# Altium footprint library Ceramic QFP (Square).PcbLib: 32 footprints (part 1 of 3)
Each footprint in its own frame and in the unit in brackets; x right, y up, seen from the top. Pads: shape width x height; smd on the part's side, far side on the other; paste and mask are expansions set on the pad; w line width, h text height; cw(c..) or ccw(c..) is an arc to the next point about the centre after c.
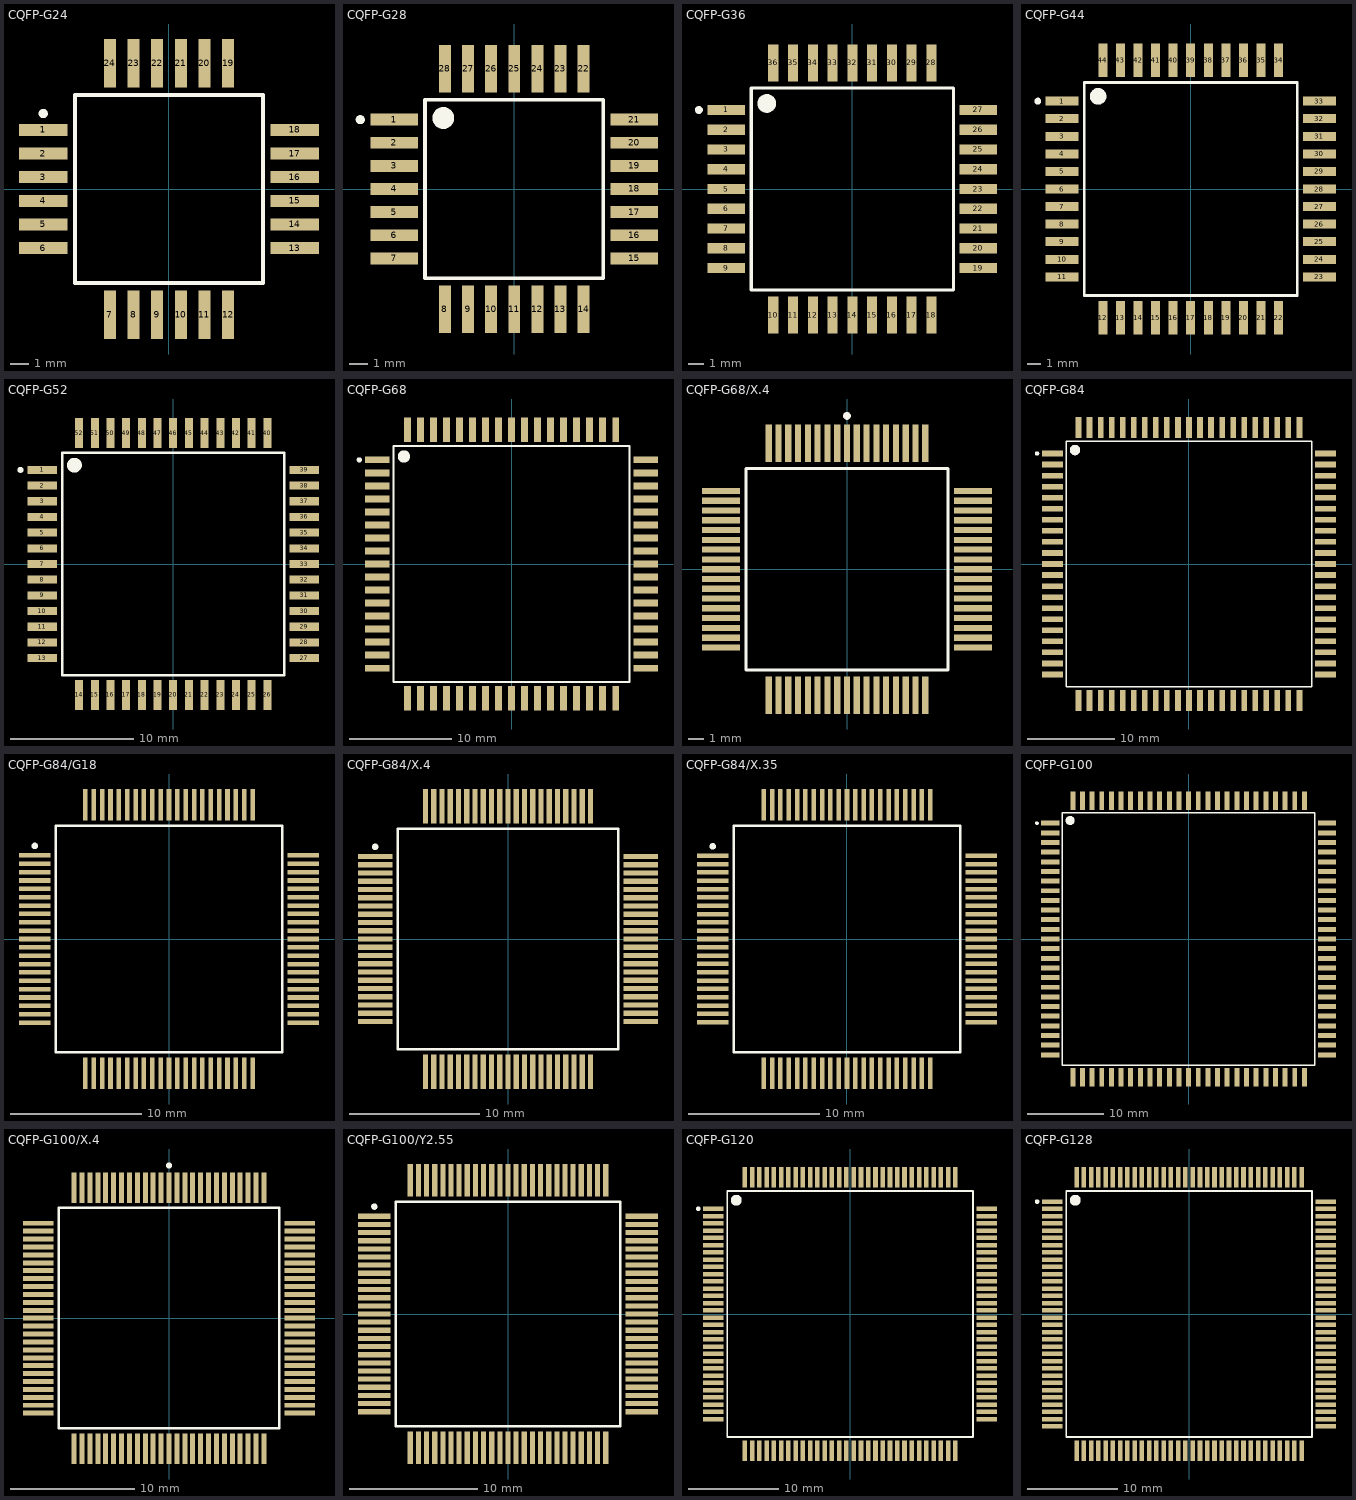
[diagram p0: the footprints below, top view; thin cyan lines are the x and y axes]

## CQFP-G24 [mm]
pads (24):
  rect 2.6x0.65 smd: 1(-6.75,3.175) 2(-6.75,1.905) 3(-6.75,0.635) 4(-6.75,-0.635) 5(-6.75,-1.905) 6(-6.75,-3.175) 13(6.75,-3.175) 14(6.75,-1.905) 15(6.75,-0.635) 16(6.75,0.635) 17(6.75,1.905) 18(6.75,3.175)
  rect 0.65x2.6 smd: 7(-3.175,-6.75) 8(-1.905,-6.75) 9(-0.635,-6.75) 10(0.635,-6.75) 11(1.905,-6.75) 12(3.175,-6.75) 19(3.175,6.75) 20(1.905,6.75) 21(0.635,6.75) 22(-0.635,6.75) 23(-1.905,6.75) 24(-3.175,6.75)
Top Overlay:
  circle w0.25: c-6.75,4.05 r0.125
  lines w0.2: -5.05,-5.05 -5.05,5.05 5.05,5.05 5.05,-5.05 -5.05,-5.05

## CQFP-G28 [mm]
pads (28):
  rect 2.6x0.65 smd: 1(-6.6,3.81) 2(-6.6,2.54) 3(-6.6,1.27) 4(-6.6,0) 5(-6.6,-1.27) 6(-6.6,-2.54) 7(-6.6,-3.81) 15(6.6,-3.81) 16(6.6,-2.54) 17(6.6,-1.27) 18(6.6,0) 19(6.6,1.27) 20(6.6,2.54) 21(6.6,3.81)
  rect 0.65x2.6 smd: 8(-3.81,-6.6) 9(-2.54,-6.6) 10(-1.27,-6.6) 11(0,-6.6) 12(1.27,-6.6) 13(2.54,-6.6) 14(3.81,-6.6) 22(3.81,6.6) 23(2.54,6.6) 24(1.27,6.6) 25(0,6.6) 26(-1.27,6.6) 27(-2.54,6.6) 28(-3.81,6.6)
Top Overlay:
  circle w0.25: c-8.46,3.81 r0.125
  circle w0.6: c-3.9,3.9 r0.3
  lines w0.2: -4.9,-4.9 4.9,-4.9 4.9,4.9 -4.9,4.9 -4.9,-4.9

## CQFP-G36 [mm]
pads (36):
  rect 2.4x0.65 smd: 1(-8.1,5.08) 2(-8.1,3.81) 3(-8.1,2.54) 4(-8.1,1.27) 5(-8.1,0) 6(-8.1,-1.27) 7(-8.1,-2.54) 8(-8.1,-3.81) 9(-8.1,-5.08) 19(8.1,-5.08) 20(8.1,-3.81) 21(8.1,-2.54) 22(8.1,-1.27) 23(8.1,0) 24(8.1,1.27) 25(8.1,2.54) 26(8.1,3.81) 27(8.1,5.08)
  rect 0.65x2.4 smd: 10(-5.08,-8.1) 11(-3.81,-8.1) 12(-2.54,-8.1) 13(-1.27,-8.1) 14(0,-8.1) 15(1.27,-8.1) 16(2.54,-8.1) 17(3.81,-8.1) 18(5.08,-8.1) 28(5.08,8.1) 29(3.81,8.1) 30(2.54,8.1) 31(1.27,8.1) 32(0,8.1) 33(-1.27,8.1) 34(-2.54,8.1) 35(-3.81,8.1) 36(-5.08,8.1)
Top Overlay:
  circle w0.25: c-9.86,5.08 r0.125
  circle w0.6: c-5.5,5.5 r0.3
  lines w0.2: -6.5,-6.5 6.5,-6.5 6.5,6.5 -6.5,6.5 -6.5,-6.5

## CQFP-G44 [mm]
pads (44):
  rect 2.4x0.65 smd: 1(-9.3,6.35) 2(-9.3,5.08) 3(-9.3,3.81) 4(-9.3,2.54) 5(-9.3,1.27) 6(-9.3,0) 7(-9.3,-1.27) 8(-9.3,-2.54) 9(-9.3,-3.81) 10(-9.3,-5.08) 11(-9.3,-6.35) 23(9.3,-6.35) 24(9.3,-5.08) 25(9.3,-3.81) 26(9.3,-2.54) 27(9.3,-1.27) 28(9.3,0) 29(9.3,1.27) 30(9.3,2.54) 31(9.3,3.81) 32(9.3,5.08) 33(9.3,6.35)
  rect 0.65x2.4 smd: 12(-6.35,-9.3) 13(-5.08,-9.3) 14(-3.81,-9.3) 15(-2.54,-9.3) 16(-1.27,-9.3) 17(0,-9.3) 18(1.27,-9.3) 19(2.54,-9.3) 20(3.81,-9.3) 21(5.08,-9.3) 22(6.35,-9.3) 34(6.35,9.3) 35(5.08,9.3) 36(3.81,9.3) 37(2.54,9.3) 38(1.27,9.3) 39(0,9.3) 40(-1.27,9.3) 41(-2.54,9.3) 42(-3.81,9.3) 43(-5.08,9.3) 44(-6.35,9.3)
Top Overlay:
  circle w0.6: c-6.7,6.7 r0.3
  circle w0.25: c-11.06,6.35 r0.125
  lines w0.2: -7.7,-7.7 -7.7,7.7 7.7,7.7 7.7,-7.7 -7.7,-7.7

## CQFP-G52 [mm]
pads (52):
  rect 2.4x0.65 smd: 1(-10.6,7.62) 2(-10.6,6.35) 3(-10.6,5.08) 4(-10.6,3.81) 5(-10.6,2.54) 6(-10.6,1.27) 7(-10.6,0) 8(-10.6,-1.27) 9(-10.6,-2.54) 10(-10.6,-3.81) 11(-10.6,-5.08) 12(-10.6,-6.35) 13(-10.6,-7.62) 27(10.6,-7.62) 28(10.6,-6.35) 29(10.6,-5.08) 30(10.6,-3.81) 31(10.6,-2.54) 32(10.6,-1.27) 33(10.6,0) 34(10.6,1.27) 35(10.6,2.54) 36(10.6,3.81) 37(10.6,5.08) 38(10.6,6.35) 39(10.6,7.62)
  rect 0.65x2.4 smd: 14(-7.62,-10.6) 15(-6.35,-10.6) 16(-5.08,-10.6) 17(-3.81,-10.6) 18(-2.54,-10.6) 19(-1.27,-10.6) 20(0,-10.6) 21(1.27,-10.6) 22(2.54,-10.6) 23(3.81,-10.6) 24(5.08,-10.6) 25(6.35,-10.6) 26(7.62,-10.6) 40(7.62,10.6) 41(6.35,10.6) 42(5.08,10.6) 43(3.81,10.6) 44(2.54,10.6) 45(1.27,10.6) 46(0,10.6) 47(-1.27,10.6) 48(-2.54,10.6) 49(-3.81,10.6) 50(-5.08,10.6) 51(-6.35,10.6) 52(-7.62,10.6)
Top Overlay:
  circle w0.6: c-8,8 r0.3
  circle w0.25: c-12.36,7.62 r0.125
  lines w0.2: -9,-9 -9,9 9,9 9,-9 -9,-9

## CQFP-G68 [mm]
pads (68):
  rect 2.4x0.65 smd: 1(-13.1,10.16) 2(-13.1,8.89) 3(-13.1,7.62) 4(-13.1,6.35) 5(-13.1,5.08) 6(-13.1,3.81) 7(-13.1,2.54) 8(-13.1,1.27) 9(-13.1,0) 10(-13.1,-1.27) 11(-13.1,-2.54) 12(-13.1,-3.81) 13(-13.1,-5.08) 14(-13.1,-6.35) 15(-13.1,-7.62) 16(-13.1,-8.89) 17(-13.1,-10.16) 35(13.1,-10.16) 36(13.1,-8.89) 37(13.1,-7.62) 38(13.1,-6.35) 39(13.1,-5.08) 40(13.1,-3.81) 41(13.1,-2.54) 42(13.1,-1.27) 43(13.1,0) 44(13.1,1.27) 45(13.1,2.54) 46(13.1,3.81) 47(13.1,5.08) 48(13.1,6.35) 49(13.1,7.62) 50(13.1,8.89) 51(13.1,10.16)
  rect 0.65x2.4 smd: 18(-10.16,-13.1) 19(-8.89,-13.1) 20(-7.62,-13.1) 21(-6.35,-13.1) 22(-5.08,-13.1) 23(-3.81,-13.1) 24(-2.54,-13.1) 25(-1.27,-13.1) 26(0,-13.1) 27(1.27,-13.1) 28(2.54,-13.1) 29(3.81,-13.1) 30(5.08,-13.1) 31(6.35,-13.1) 32(7.62,-13.1) 33(8.89,-13.1) 34(10.16,-13.1) 52(10.16,13.1) 53(8.89,13.1) 54(7.62,13.1) 55(6.35,13.1) 56(5.08,13.1) 57(3.81,13.1) 58(2.54,13.1) 59(1.27,13.1) 60(0,13.1) 61(-1.27,13.1) 62(-2.54,13.1) 63(-3.81,13.1) 64(-5.08,13.1) 65(-6.35,13.1) 66(-7.62,13.1) 67(-8.89,13.1) 68(-10.16,13.1)
Top Overlay:
  circle w0.25: c-14.86,10.16 r0.125
  circle w0.6: c-10.5,10.5 r0.3
  lines w0.2: -11.5,-11.5 11.5,-11.5 11.5,11.5 -11.5,11.5 -11.5,-11.5

## CQFP-G68/X.4 [mm]
pads (68):
  rect 0.4x2.45 smd: 1(0,8.175) 2(-0.635,8.175) 3(-1.27,8.175) 4(-1.905,8.175) 5(-2.54,8.175) 6(-3.175,8.175) 7(-3.81,8.175) 8(-4.445,8.175) 9(-5.08,8.175) 27(-5.08,-8.175) 28(-4.445,-8.175) 29(-3.81,-8.175) 30(-3.175,-8.175) 31(-2.54,-8.175) 32(-1.905,-8.175) 33(-1.27,-8.175) 34(-0.635,-8.175) 35(0,-8.175) 36(0.635,-8.175) 37(1.27,-8.175) 38(1.905,-8.175) 39(2.54,-8.175) 40(3.175,-8.175) 41(3.81,-8.175) 42(4.445,-8.175) 43(5.08,-8.175) 61(5.08,8.175) 62(4.445,8.175) 63(3.81,8.175) 64(3.175,8.175) 65(2.54,8.175) 66(1.905,8.175) 67(1.27,8.175) 68(0.635,8.175)
  rect 2.45x0.4 smd: 10(-8.175,5.08) 11(-8.175,4.445) 12(-8.175,3.81) 13(-8.175,3.175) 14(-8.175,2.54) 15(-8.175,1.905) 16(-8.175,1.27) 17(-8.175,0.635) 18(-8.175,0) 19(-8.175,-0.635) 20(-8.175,-1.27) 21(-8.175,-1.905) 22(-8.175,-2.54) 23(-8.175,-3.175) 24(-8.175,-3.81) 25(-8.175,-4.445) 26(-8.175,-5.08) 44(8.175,-5.08) 45(8.175,-4.445) 46(8.175,-3.81) 47(8.175,-3.175) 48(8.175,-2.54) 49(8.175,-1.905) 50(8.175,-1.27) 51(8.175,-0.635) 52(8.175,0) 53(8.175,0.635) 54(8.175,1.27) 55(8.175,1.905) 56(8.175,2.54) 57(8.175,3.175) 58(8.175,3.81) 59(8.175,4.445) 60(8.175,5.08)
Top Overlay:
  circle w0.25: c0,9.95 r0.125
  lines w0.2: -6.55,-6.55 -6.55,6.55 6.55,6.55 6.55,-6.55 -6.55,-6.55

## CQFP-G84 [mm]
pads (84):
  rect 2.4x0.65 smd: 1(-15.7,12.7) 2(-15.7,11.43) 3(-15.7,10.16) 4(-15.7,8.89) 5(-15.7,7.62) 6(-15.7,6.35) 7(-15.7,5.08) 8(-15.7,3.81) 9(-15.7,2.54) 10(-15.7,1.27) 11(-15.7,0) 12(-15.7,-1.27) 13(-15.7,-2.54) 14(-15.7,-3.81) 15(-15.7,-5.08) 16(-15.7,-6.35) 17(-15.7,-7.62) 18(-15.7,-8.89) 19(-15.7,-10.16) 20(-15.7,-11.43) 21(-15.7,-12.7) 43(15.7,-12.7) 44(15.7,-11.43) 45(15.7,-10.16) 46(15.7,-8.89) 47(15.7,-7.62) 48(15.7,-6.35) 49(15.7,-5.08) 50(15.7,-3.81) 51(15.7,-2.54) 52(15.7,-1.27) 53(15.7,0) 54(15.7,1.27) 55(15.7,2.54) 56(15.7,3.81) 57(15.7,5.08) 58(15.7,6.35) 59(15.7,7.62) 60(15.7,8.89) 61(15.7,10.16) 62(15.7,11.43) 63(15.7,12.7)
  rect 0.65x2.4 smd: 22(-12.7,-15.7) 23(-11.43,-15.7) 24(-10.16,-15.7) 25(-8.89,-15.7) 26(-7.62,-15.7) 27(-6.35,-15.7) 28(-5.08,-15.7) 29(-3.81,-15.7) 30(-2.54,-15.7) 31(-1.27,-15.7) 32(0,-15.7) 33(1.27,-15.7) 34(2.54,-15.7) 35(3.81,-15.7) 36(5.08,-15.7) 37(6.35,-15.7) 38(7.62,-15.7) 39(8.89,-15.7) 40(10.16,-15.7) 41(11.43,-15.7) 42(12.7,-15.7) 64(12.7,15.7) 65(11.43,15.7) 66(10.16,15.7) 67(8.89,15.7) 68(7.62,15.7) 69(6.35,15.7) 70(5.08,15.7) 71(3.81,15.7) 72(2.54,15.7) 73(1.27,15.7) 74(0,15.7) 75(-1.27,15.7) 76(-2.54,15.7) 77(-3.81,15.7) 78(-5.08,15.7) 79(-6.35,15.7) 80(-7.62,15.7) 81(-8.89,15.7) 82(-10.16,15.7) 83(-11.43,15.7) 84(-12.7,15.7)
Top Overlay:
  circle w0.25: c-17.46,12.7 r0.125
  circle w0.6: c-13.1,13.1 r0.3
  lines w0.2: -14.1,-14.1 14.1,-14.1 14.1,14.1 -14.1,14.1 -14.1,-14.1

## CQFP-G84/G18 [mm]
pads (84):
  rect 2.4x0.35 smd: 1(-10.2,6.35) 2(-10.2,5.715) 3(-10.2,5.08) 4(-10.2,4.445) 5(-10.2,3.81) 6(-10.2,3.175) 7(-10.2,2.54) 8(-10.2,1.905) 9(-10.2,1.27) 10(-10.2,0.635) 11(-10.2,0) 12(-10.2,-0.635) 13(-10.2,-1.27) 14(-10.2,-1.905) 15(-10.2,-2.54) 16(-10.2,-3.175) 17(-10.2,-3.81) 18(-10.2,-4.445) 19(-10.2,-5.08) 20(-10.2,-5.715) 21(-10.2,-6.35) 43(10.2,-6.35) 44(10.2,-5.715) 45(10.2,-5.08) 46(10.2,-4.445) 47(10.2,-3.81) 48(10.2,-3.175) 49(10.2,-2.54) 50(10.2,-1.905) 51(10.2,-1.27) 52(10.2,-0.635) 53(10.2,0) 54(10.2,0.635) 55(10.2,1.27) 56(10.2,1.905) 57(10.2,2.54) 58(10.2,3.175) 59(10.2,3.81) 60(10.2,4.445) 61(10.2,5.08) 62(10.2,5.715) 63(10.2,6.35)
  rect 0.35x2.4 smd: 22(-6.35,-10.2) 23(-5.715,-10.2) 24(-5.08,-10.2) 25(-4.445,-10.2) 26(-3.81,-10.2) 27(-3.175,-10.2) 28(-2.54,-10.2) 29(-1.905,-10.2) 30(-1.27,-10.2) 31(-0.635,-10.2) 32(0,-10.2) 33(0.635,-10.2) 34(1.27,-10.2) 35(1.905,-10.2) 36(2.54,-10.2) 37(3.175,-10.2) 38(3.81,-10.2) 39(4.445,-10.2) 40(5.08,-10.2) 41(5.715,-10.2) 42(6.35,-10.2) 64(6.35,10.2) 65(5.715,10.2) 66(5.08,10.2) 67(4.445,10.2) 68(3.81,10.2) 69(3.175,10.2) 70(2.54,10.2) 71(1.905,10.2) 72(1.27,10.2) 73(0.635,10.2) 74(0,10.2) 75(-0.635,10.2) 76(-1.27,10.2) 77(-1.905,10.2) 78(-2.54,10.2) 79(-3.175,10.2) 80(-3.81,10.2) 81(-4.445,10.2) 82(-5.08,10.2) 83(-5.715,10.2) 84(-6.35,10.2)
Top Overlay:
  circle w0.25: c-10.2,7.075 r0.125
  lines w0.2: -8.6,-8.6 8.6,-8.6 8.6,8.6 -8.6,8.6 -8.6,-8.6

## CQFP-G84/X.4 [mm]
pads (84):
  rect 2.65x0.4 smd: 1(-10.225,6.35) 2(-10.225,5.715) 3(-10.225,5.08) 4(-10.225,4.445) 5(-10.225,3.81) 6(-10.225,3.175) 7(-10.225,2.54) 8(-10.225,1.905) 9(-10.225,1.27) 10(-10.225,0.635) 11(-10.225,0) 12(-10.225,-0.635) 13(-10.225,-1.27) 14(-10.225,-1.905) 15(-10.225,-2.54) 16(-10.225,-3.175) 17(-10.225,-3.81) 18(-10.225,-4.445) 19(-10.225,-5.08) 20(-10.225,-5.715) 21(-10.225,-6.35) 43(10.225,-6.35) 44(10.225,-5.715) 45(10.225,-5.08) 46(10.225,-4.445) 47(10.225,-3.81) 48(10.225,-3.175) 49(10.225,-2.54) 50(10.225,-1.905) 51(10.225,-1.27) 52(10.225,-0.635) 53(10.225,0) 54(10.225,0.635) 55(10.225,1.27) 56(10.225,1.905) 57(10.225,2.54) 58(10.225,3.175) 59(10.225,3.81) 60(10.225,4.445) 61(10.225,5.08) 62(10.225,5.715) 63(10.225,6.35)
  rect 0.4x2.65 smd: 22(-6.35,-10.225) 23(-5.715,-10.225) 24(-5.08,-10.225) 25(-4.445,-10.225) 26(-3.81,-10.225) 27(-3.175,-10.225) 28(-2.54,-10.225) 29(-1.905,-10.225) 30(-1.27,-10.225) 31(-0.635,-10.225) 32(0,-10.225) 33(0.635,-10.225) 34(1.27,-10.225) 35(1.905,-10.225) 36(2.54,-10.225) 37(3.175,-10.225) 38(3.81,-10.225) 39(4.445,-10.225) 40(5.08,-10.225) 41(5.715,-10.225) 42(6.35,-10.225) 64(6.35,10.225) 65(5.715,10.225) 66(5.08,10.225) 67(4.445,10.225) 68(3.81,10.225) 69(3.175,10.225) 70(2.54,10.225) 71(1.905,10.225) 72(1.27,10.225) 73(0.635,10.225) 74(0,10.225) 75(-0.635,10.225) 76(-1.27,10.225) 77(-1.905,10.225) 78(-2.54,10.225) 79(-3.175,10.225) 80(-3.81,10.225) 81(-4.445,10.225) 82(-5.08,10.225) 83(-5.715,10.225) 84(-6.35,10.225)
Top Overlay:
  circle w0.25: c-10.225,7.1 r0.125
  lines w0.2: -8.5,-8.5 8.5,-8.5 8.5,8.5 -8.5,8.5 -8.5,-8.5

## CQFP-G84/X.35 [mm]
pads (84):
  rect 2.4x0.35 smd: 1(-10.25,6.35) 2(-10.25,5.715) 3(-10.25,5.08) 4(-10.25,4.445) 5(-10.25,3.81) 6(-10.25,3.175) 7(-10.25,2.54) 8(-10.25,1.905) 9(-10.25,1.27) 10(-10.25,0.635) 11(-10.25,0) 12(-10.25,-0.635) 13(-10.25,-1.27) 14(-10.25,-1.905) 15(-10.25,-2.54) 16(-10.25,-3.175) 17(-10.25,-3.81) 18(-10.25,-4.445) 19(-10.25,-5.08) 20(-10.25,-5.715) 21(-10.25,-6.35) 43(10.25,-6.35) 44(10.25,-5.715) 45(10.25,-5.08) 46(10.25,-4.445) 47(10.25,-3.81) 48(10.25,-3.175) 49(10.25,-2.54) 50(10.25,-1.905) 51(10.25,-1.27) 52(10.25,-0.635) 53(10.25,0) 54(10.25,0.635) 55(10.25,1.27) 56(10.25,1.905) 57(10.25,2.54) 58(10.25,3.175) 59(10.25,3.81) 60(10.25,4.445) 61(10.25,5.08) 62(10.25,5.715) 63(10.25,6.35)
  rect 0.35x2.4 smd: 22(-6.35,-10.25) 23(-5.715,-10.25) 24(-5.08,-10.25) 25(-4.445,-10.25) 26(-3.81,-10.25) 27(-3.175,-10.25) 28(-2.54,-10.25) 29(-1.905,-10.25) 30(-1.27,-10.25) 31(-0.635,-10.25) 32(0,-10.25) 33(0.635,-10.25) 34(1.27,-10.25) 35(1.905,-10.25) 36(2.54,-10.25) 37(3.175,-10.25) 38(3.81,-10.25) 39(4.445,-10.25) 40(5.08,-10.25) 41(5.715,-10.25) 42(6.35,-10.25) 64(6.35,10.25) 65(5.715,10.25) 66(5.08,10.25) 67(4.445,10.25) 68(3.81,10.25) 69(3.175,10.25) 70(2.54,10.25) 71(1.905,10.25) 72(1.27,10.25) 73(0.635,10.25) 74(0,10.25) 75(-0.635,10.25) 76(-1.27,10.25) 77(-1.905,10.25) 78(-2.54,10.25) 79(-3.175,10.25) 80(-3.81,10.25) 81(-4.445,10.25) 82(-5.08,10.25) 83(-5.715,10.25) 84(-6.35,10.25)
Top Overlay:
  circle w0.25: c-10.25,7.075 r0.125
  lines w0.2: -8.65,-8.65 -8.65,8.65 8.65,8.65 8.65,-8.65 -8.65,-8.65

## CQFP-G100 [mm]
pads (100):
  rect 2.4x0.65 smd: 1(-18.2,15.24) 2(-18.2,13.97) 3(-18.2,12.7) 4(-18.2,11.43) 5(-18.2,10.16) 6(-18.2,8.89) 7(-18.2,7.62) 8(-18.2,6.35) 9(-18.2,5.08) 10(-18.2,3.81) 11(-18.2,2.54) 12(-18.2,1.27) 13(-18.2,0) 14(-18.2,-1.27) 15(-18.2,-2.54) 16(-18.2,-3.81) 17(-18.2,-5.08) 18(-18.2,-6.35) 19(-18.2,-7.62) 20(-18.2,-8.89) 21(-18.2,-10.16) 22(-18.2,-11.43) 23(-18.2,-12.7) 24(-18.2,-13.97) 25(-18.2,-15.24) 51(18.2,-15.24) 52(18.2,-13.97) 53(18.2,-12.7) 54(18.2,-11.43) 55(18.2,-10.16) 56(18.2,-8.89) 57(18.2,-7.62) 58(18.2,-6.35) 59(18.2,-5.08) 60(18.2,-3.81) 61(18.2,-2.54) 62(18.2,-1.27) 63(18.2,0) 64(18.2,1.27) 65(18.2,2.54) 66(18.2,3.81) 67(18.2,5.08) 68(18.2,6.35) 69(18.2,7.62) 70(18.2,8.89) 71(18.2,10.16) 72(18.2,11.43) 73(18.2,12.7) 74(18.2,13.97) 75(18.2,15.24)
  rect 0.65x2.4 smd: 26(-15.24,-18.2) 27(-13.97,-18.2) 28(-12.7,-18.2) 29(-11.43,-18.2) 30(-10.16,-18.2) 31(-8.89,-18.2) 32(-7.62,-18.2) 33(-6.35,-18.2) 34(-5.08,-18.2) 35(-3.81,-18.2) 36(-2.54,-18.2) 37(-1.27,-18.2) 38(0,-18.2) 39(1.27,-18.2) 40(2.54,-18.2) 41(3.81,-18.2) 42(5.08,-18.2) 43(6.35,-18.2) 44(7.62,-18.2) 45(8.89,-18.2) 46(10.16,-18.2) 47(11.43,-18.2) 48(12.7,-18.2) 49(13.97,-18.2) 50(15.24,-18.2) 76(15.24,18.2) 77(13.97,18.2) 78(12.7,18.2) 79(11.43,18.2) 80(10.16,18.2) 81(8.89,18.2) 82(7.62,18.2) 83(6.35,18.2) 84(5.08,18.2) 85(3.81,18.2) 86(2.54,18.2) 87(1.27,18.2) 88(0,18.2) 89(-1.27,18.2) 90(-2.54,18.2) 91(-3.81,18.2) 92(-5.08,18.2) 93(-6.35,18.2) 94(-7.62,18.2) 95(-8.89,18.2) 96(-10.16,18.2) 97(-11.43,18.2) 98(-12.7,18.2) 99(-13.97,18.2) 100(-15.24,18.2)
Top Overlay:
  circle w0.25: c-19.96,15.24 r0.125
  circle w0.6: c-15.6,15.6 r0.3
  lines w0.2: -16.6,-16.6 16.6,-16.6 16.6,16.6 -16.6,16.6 -16.6,-16.6

## CQFP-G100/X.4 [mm]
pads (100):
  rect 0.4x2.45 smd: 1(0,10.475) 2(-0.635,10.475) 3(-1.27,10.475) 4(-1.905,10.475) 5(-2.54,10.475) 6(-3.175,10.475) 7(-3.81,10.475) 8(-4.445,10.475) 9(-5.08,10.475) 10(-5.715,10.475) 11(-6.35,10.475) 12(-6.985,10.475) 13(-7.62,10.475) 39(-7.62,-10.475) 40(-6.985,-10.475) 41(-6.35,-10.475) 42(-5.715,-10.475) 43(-5.08,-10.475) 44(-4.445,-10.475) 45(-3.81,-10.475) 46(-3.175,-10.475) 47(-2.54,-10.475) 48(-1.905,-10.475) 49(-1.27,-10.475) 50(-0.635,-10.475) 51(0,-10.475) 52(0.635,-10.475) 53(1.27,-10.475) 54(1.905,-10.475) 55(2.54,-10.475) 56(3.175,-10.475) 57(3.81,-10.475) 58(4.445,-10.475) 59(5.08,-10.475) 60(5.715,-10.475) 61(6.35,-10.475) 62(6.985,-10.475) 63(7.62,-10.475) 89(7.62,10.475) 90(6.985,10.475) 91(6.35,10.475) 92(5.715,10.475) 93(5.08,10.475) 94(4.445,10.475) 95(3.81,10.475) 96(3.175,10.475) 97(2.54,10.475) 98(1.905,10.475) 99(1.27,10.475) 100(0.635,10.475)
  rect 2.45x0.4 smd: 14(-10.475,7.62) 15(-10.475,6.985) 16(-10.475,6.35) 17(-10.475,5.715) 18(-10.475,5.08) 19(-10.475,4.445) 20(-10.475,3.81) 21(-10.475,3.175) 22(-10.475,2.54) 23(-10.475,1.905) 24(-10.475,1.27) 25(-10.475,0.635) 26(-10.475,0) 27(-10.475,-0.635) 28(-10.475,-1.27) 29(-10.475,-1.905) 30(-10.475,-2.54) 31(-10.475,-3.175) 32(-10.475,-3.81) 33(-10.475,-4.445) 34(-10.475,-5.08) 35(-10.475,-5.715) 36(-10.475,-6.35) 37(-10.475,-6.985) 38(-10.475,-7.62) 64(10.475,-7.62) 65(10.475,-6.985) 66(10.475,-6.35) 67(10.475,-5.715) 68(10.475,-5.08) 69(10.475,-4.445) 70(10.475,-3.81) 71(10.475,-3.175) 72(10.475,-2.54) 73(10.475,-1.905) 74(10.475,-1.27) 75(10.475,-0.635) 76(10.475,0) 77(10.475,0.635) 78(10.475,1.27) 79(10.475,1.905) 80(10.475,2.54) 81(10.475,3.175) 82(10.475,3.81) 83(10.475,4.445) 84(10.475,5.08) 85(10.475,5.715) 86(10.475,6.35) 87(10.475,6.985) 88(10.475,7.62)
Top Overlay:
  circle w0.25: c0,12.25 r0.125
  lines w0.2: -8.85,-8.85 -8.85,8.85 8.85,8.85 8.85,-8.85 -8.85,-8.85

## CQFP-G100/Y2.55 [mm]
pads (100):
  rect 2.55x0.4 smd: 1(-10.425,7.62) 2(-10.425,6.985) 3(-10.425,6.35) 4(-10.425,5.715) 5(-10.425,5.08) 6(-10.425,4.445) 7(-10.425,3.81) 8(-10.425,3.175) 9(-10.425,2.54) 10(-10.425,1.905) 11(-10.425,1.27) 12(-10.425,0.635) 13(-10.425,0) 14(-10.425,-0.635) 15(-10.425,-1.27) 16(-10.425,-1.905) 17(-10.425,-2.54) 18(-10.425,-3.175) 19(-10.425,-3.81) 20(-10.425,-4.445) 21(-10.425,-5.08) 22(-10.425,-5.715) 23(-10.425,-6.35) 24(-10.425,-6.985) 25(-10.425,-7.62) 51(10.425,-7.62) 52(10.425,-6.985) 53(10.425,-6.35) 54(10.425,-5.715) 55(10.425,-5.08) 56(10.425,-4.445) 57(10.425,-3.81) 58(10.425,-3.175) 59(10.425,-2.54) 60(10.425,-1.905) 61(10.425,-1.27) 62(10.425,-0.635) 63(10.425,0) 64(10.425,0.635) 65(10.425,1.27) 66(10.425,1.905) 67(10.425,2.54) 68(10.425,3.175) 69(10.425,3.81) 70(10.425,4.445) 71(10.425,5.08) 72(10.425,5.715) 73(10.425,6.35) 74(10.425,6.985) 75(10.425,7.62)
  rect 0.4x2.55 smd: 26(-7.62,-10.425) 27(-6.985,-10.425) 28(-6.35,-10.425) 29(-5.715,-10.425) 30(-5.08,-10.425) 31(-4.445,-10.425) 32(-3.81,-10.425) 33(-3.175,-10.425) 34(-2.54,-10.425) 35(-1.905,-10.425) 36(-1.27,-10.425) 37(-0.635,-10.425) 38(0,-10.425) 39(0.635,-10.425) 40(1.27,-10.425) 41(1.905,-10.425) 42(2.54,-10.425) 43(3.175,-10.425) 44(3.81,-10.425) 45(4.445,-10.425) 46(5.08,-10.425) 47(5.715,-10.425) 48(6.35,-10.425) 49(6.985,-10.425) 50(7.62,-10.425) 76(7.62,10.425) 77(6.985,10.425) 78(6.35,10.425) 79(5.715,10.425) 80(5.08,10.425) 81(4.445,10.425) 82(3.81,10.425) 83(3.175,10.425) 84(2.54,10.425) 85(1.905,10.425) 86(1.27,10.425) 87(0.635,10.425) 88(0,10.425) 89(-0.635,10.425) 90(-1.27,10.425) 91(-1.905,10.425) 92(-2.54,10.425) 93(-3.175,10.425) 94(-3.81,10.425) 95(-4.445,10.425) 96(-5.08,10.425) 97(-5.715,10.425) 98(-6.35,10.425) 99(-6.985,10.425) 100(-7.62,10.425)
Top Overlay:
  circle w0.25: c-10.425,8.37 r0.125
  lines w0.2: -8.75,-8.75 -8.75,8.75 8.75,8.75 8.75,-8.75 -8.75,-8.75

## CQFP-G120 [mm]
pads (120):
  rect 2.25x0.5 smd: 1(-15.069,11.6) 2(-15.069,10.8) 3(-15.069,10) 4(-15.069,9.2) 5(-15.069,8.4) 6(-15.069,7.6) 7(-15.069,6.8) 8(-15.069,6) 9(-15.069,5.2) 10(-15.069,4.4) 11(-15.069,3.6) 12(-15.069,2.8) 13(-15.069,2) 14(-15.081,1.195) 15(-15.069,0.4) 16(-15.069,-0.4) 17(-15.069,-1.2) 18(-15.069,-2) 19(-15.069,-2.8) 20(-15.069,-3.6) 21(-15.069,-4.4) 22(-15.069,-5.2) 23(-15.069,-6) 24(-15.069,-6.8) 25(-15.069,-7.6) 26(-15.069,-8.4) 27(-15.069,-9.2) 28(-15.069,-10) 29(-15.069,-10.8) 30(-15.069,-11.6) 61(15.081,-11.6) 62(15.081,-10.8) 63(15.081,-10) 64(15.081,-9.2) 65(15.081,-8.4) 66(15.081,-7.6) 67(15.081,-6.8) 68(15.081,-6) 69(15.081,-5.2) 70(15.081,-4.4) 71(15.081,-3.6) 72(15.081,-2.8) 73(15.081,-2) 74(15.081,-1.2) 75(15.081,-0.4) 76(15.081,0.4) 77(15.081,1.2) 78(15.081,2) 79(15.081,2.8) 80(15.081,3.6) 81(15.081,4.4) 82(15.081,5.2) 83(15.081,6) 84(15.081,6.8) 85(15.081,7.6) 86(15.081,8.4) 87(15.081,9.2) 88(15.081,10) 89(15.081,10.8) 90(15.081,11.6)
  rect 0.5x2.25 smd: 31(-11.594,-15.075) 32(-10.794,-15.075) 33(-9.994,-15.075) 34(-9.194,-15.075) 35(-8.394,-15.075) 36(-7.594,-15.075) 37(-6.794,-15.075) 38(-5.994,-15.075) 39(-5.194,-15.075) 40(-4.394,-15.075) 41(-3.594,-15.075) 42(-2.794,-15.075) 43(-1.994,-15.075) 44(-1.194,-15.075) 45(-0.394,-15.075) 46(0.406,-15.075) 47(1.206,-15.075) 48(2.006,-15.075) 49(2.806,-15.075) 50(3.606,-15.075) 51(4.406,-15.075) 52(5.206,-15.075) 53(6.006,-15.075) 54(6.806,-15.075) 55(7.606,-15.075) 56(8.406,-15.075) 57(9.206,-15.075) 58(10.006,-15.075) 59(10.806,-15.075) 60(11.606,-15.075) 91(11.606,15.075) 92(10.806,15.075) 93(10.006,15.075) 94(9.206,15.075) 95(8.406,15.075) 96(7.606,15.075) 97(6.806,15.075) 98(6.006,15.075) 99(5.206,15.075) 100(4.406,15.075) 101(3.606,15.075) 102(2.806,15.075) 103(2.006,15.075) 104(1.206,15.075) 105(0.406,15.075) 106(-0.394,15.075) 107(-1.194,15.075) 108(-1.994,15.075) 109(-2.794,15.075) 110(-3.594,15.075) 111(-4.394,15.075) 112(-5.194,15.075) 113(-5.994,15.075) 114(-6.794,15.075) 115(-7.594,15.075) 116(-8.394,15.075) 117(-9.194,15.075) 118(-9.994,15.075) 119(-10.794,15.075) 120(-11.594,15.075)
Top Overlay:
  circle w0.6: c-12.544,12.55 r0.3
  circle w0.25: c-16.754,11.6 r0.125
  lines w0.2: -13.544,-13.55 -13.544,13.55 13.556,13.55 13.556,-13.55 -13.544,-13.55

## CQFP-G128 [mm]
pads (128):
  rect 2.25x0.5 smd: 1(-15.075,12.4) 2(-15.075,11.6) 3(-15.075,10.8) 4(-15.075,10) 5(-15.075,9.2) 6(-15.075,8.4) 7(-15.075,7.6) 8(-15.075,6.8) 9(-15.075,6) 10(-15.075,5.2) 11(-15.075,4.4) 12(-15.075,3.6) 13(-15.075,2.8) 14(-15.075,2) 15(-15.075,1.2) 16(-15.075,0.4) 17(-15.075,-0.4) 18(-15.075,-1.2) 19(-15.075,-2) 20(-15.075,-2.8) 21(-15.075,-3.6) 22(-15.075,-4.4) 23(-15.075,-5.2) 24(-15.075,-6) 25(-15.075,-6.8) 26(-15.075,-7.6) 27(-15.075,-8.4) 28(-15.075,-9.2) 29(-15.075,-10) 30(-15.075,-10.8) 31(-15.075,-11.6) 32(-15.075,-12.4) 65(15.075,-12.4) 66(15.075,-11.6) 67(15.075,-10.8) 68(15.075,-10) 69(15.075,-9.2) 70(15.075,-8.4) 71(15.075,-7.6) 72(15.075,-6.8) 73(15.075,-6) 74(15.075,-5.2) 75(15.075,-4.4) 76(15.075,-3.6) 77(15.075,-2.8) 78(15.075,-2) 79(15.075,-1.2) 80(15.075,-0.4) 81(15.075,0.4) 82(15.075,1.2) 83(15.075,2) 84(15.075,2.8) 85(15.075,3.6) 86(15.075,4.4) 87(15.075,5.2) 88(15.075,6) 89(15.075,6.8) 90(15.075,7.6) 91(15.075,8.4) 92(15.075,9.2) 93(15.075,10) 94(15.075,10.8) 95(15.075,11.6) 96(15.075,12.4)
  rect 0.5x2.25 smd: 33(-12.4,-15.075) 34(-11.6,-15.075) 35(-10.8,-15.075) 36(-10,-15.075) 37(-9.2,-15.075) 38(-8.4,-15.075) 39(-7.6,-15.075) 40(-6.8,-15.075) 41(-6,-15.075) 42(-5.2,-15.075) 43(-4.4,-15.075) 44(-3.6,-15.075) 45(-2.8,-15.075) 46(-2,-15.075) 47(-1.2,-15.075) 48(-0.4,-15.075) 49(0.4,-15.075) 50(1.2,-15.075) 51(2,-15.075) 52(2.8,-15.075) 53(3.6,-15.075) 54(4.4,-15.075) 55(5.2,-15.075) 56(6,-15.075) 57(6.8,-15.075) 58(7.6,-15.075) 59(8.4,-15.075) 60(9.2,-15.075) 61(10,-15.075) 62(10.8,-15.075) 63(11.6,-15.075) 64(12.4,-15.075) 97(12.4,15.075) 98(11.6,15.075) 99(10.8,15.075) 100(10,15.075) 101(9.2,15.075) 102(8.4,15.075) 103(7.6,15.075) 104(6.8,15.075) 105(6,15.075) 106(5.2,15.075) 107(4.4,15.075) 108(3.6,15.075) 109(2.8,15.075) 110(2,15.075) 111(1.2,15.075) 112(0.4,15.075) 113(-0.4,15.075) 114(-1.2,15.075) 115(-2,15.075) 116(-2.8,15.075) 117(-3.6,15.075) 118(-4.4,15.075) 119(-5.2,15.075) 120(-6,15.075) 121(-6.8,15.075) 122(-7.6,15.075) 123(-8.4,15.075) 124(-9.2,15.075) 125(-10,15.075) 126(-10.8,15.075) 127(-11.6,15.075) 128(-12.4,15.075)
Top Overlay:
  circle w0.6: c-12.55,12.55 r0.3
  circle w0.25: c-16.76,12.4 r0.125
  lines w0.2: -13.55,-13.55 -13.55,13.55 13.55,13.55 13.55,-13.55 -13.55,-13.55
